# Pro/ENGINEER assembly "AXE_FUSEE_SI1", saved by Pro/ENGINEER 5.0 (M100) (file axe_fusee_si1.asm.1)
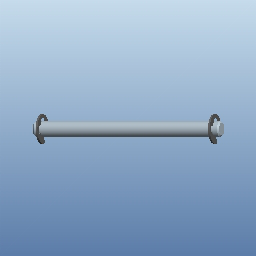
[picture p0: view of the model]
Units: millimeter Newton Second (mmNs); MM, TONNE, HOURS

Other components: AXE_FUSEE_SI1, ANNEAU_RADIAL-6X07, ANNEAU_RADIAL-6X07

Other named items: AXE_FUSEE_01, A-DROITE, A-DESSUS, A-FACE, A-R0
